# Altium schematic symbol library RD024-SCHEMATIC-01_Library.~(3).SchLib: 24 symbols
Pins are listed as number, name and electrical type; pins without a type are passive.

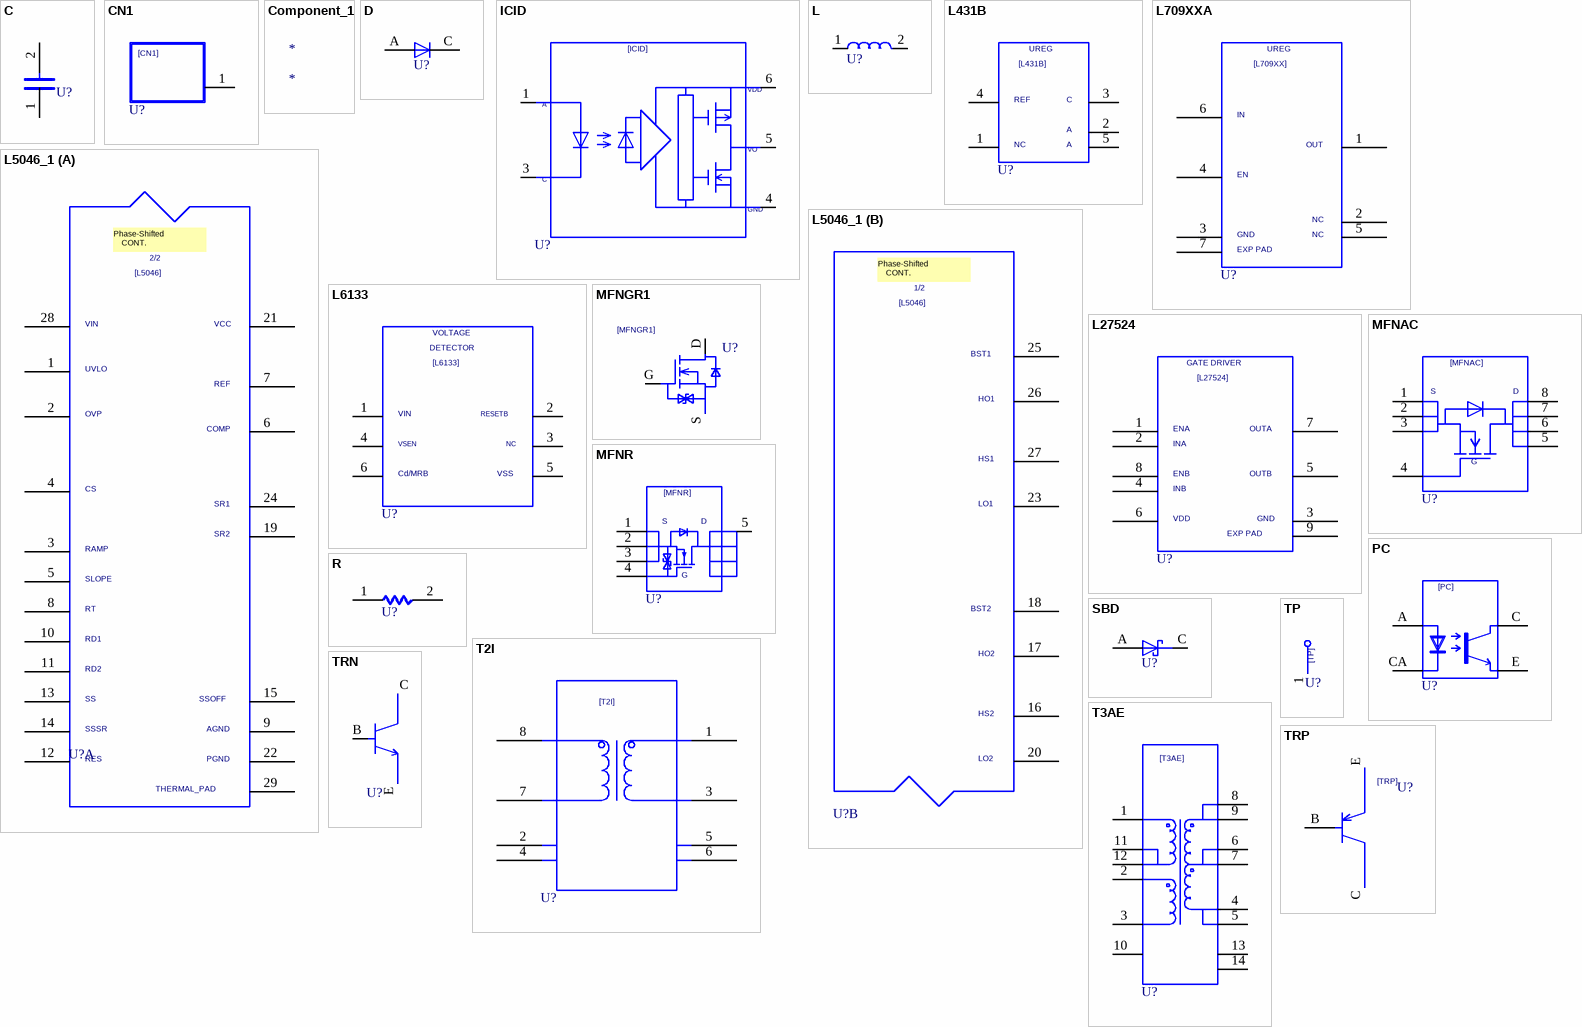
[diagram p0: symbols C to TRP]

## C
designator U?  (value not drawn)
OriginalSymbolOrigin: (2540,7620); Altium-Right: 20; Altium-Bottom: 10
pins: 1, 2

## CN1
designator U?  (value not drawn)
OriginalSymbolOrigin: (2540,12700); Altium-Right: 50; Altium-Bottom: 40
pins: 1

## Component_1
designator *

## D
designator U?  (value not drawn)
SAVEAREA0: -225,-91,12804,7836; SAVECOUNT: 3; TIME: 14:49:55; UPDATEUSER: 19870035; UPDATETIME: 14:20:16; OriginalSymbolOrigin: (5080,5080); Altium-Right: 10; Altium-Bottom: 20
pins: A, C

## ICID
designator U?  (value not drawn)
TIME: 11:37:10; UPDATEUSER: cae; UPDATETIME: 10:02:13; SAVECOUNT: 16; SAVEAREA0: -15781,-397,59072,38480; OriginalSymbolOrigin: (2540,35560); Altium-Right: 150; Altium-Bottom: 130
pins: 1, 3, 4, 5, 6

## L
designator U?  (value not drawn)
OriginalSymbolOrigin: (2540,5080); Altium-Right: 30; Altium-Bottom: 20
pins: 1, 2

## L431B
designator U?  (value not drawn)
SAVEAREA0: -12224,-318,37706,25614; TIME: 11:47:14; UPDATEUSER: cae; UPDATETIME: 15:43:57; SAVECOUNT: 6; OriginalSymbolOrigin: (5080,22860); Altium-Right: 60; Altium-Bottom: 80
pins: 1, 2, 3, 4, 5

## L709XXA
designator U?  (value not drawn)
SAVECOUNT: 38; SAVEAREA0: -24553,-450,60279,43610; TIME: 14:46:30; UPDATEUSER: cae; UPDATETIME: 12:49:59; OriginalSymbolOrigin: (7620,40640); Altium-Right: 80; Altium-Bottom: 150
pins: 1, 2, 3, 4, 5, 6, 7

## L5046_1
designator U?  (value not drawn)
SAVEAREA0: -71804,-1007,117827,97484; TIME: 14:38:41; UPDATEUSER: cae; UPDATETIME: 09:49:47; SAVECOUNT: 16; OriginalSymbolOrigin: (7620,93980); Altium-Right: 120; Altium-Bottom: 410; Altium-Bottom1: 370
part A pins: 1, 2, 3, 4, 5, 6, 7, 8, 9, 10, 11, 12, 13, 14, 15, 19, 21, 22, 24, 28, 29
part B pins: 16, 17, 18, 20, 23, 25, 26, 27

## L6133
designator U?  (value not drawn)
TIME: 13:21:52; UPDATEUSER: cae; UPDATETIME: 10:15:35; SAVECOUNT: 15; SAVEAREA0: -9663,-435,45411,35893; OriginalSymbolOrigin: (5080,33020); Altium-Right: 100; Altium-Bottom: 120
pins: 1, 2, 3, 4, 5, 6

## L27524
designator U?  (value not drawn)
SAVEAREA0: -18325,-397,56528,38480; SAVECOUNT: 17; TIME: 12:23:18; UPDATEUSER: cae; UPDATETIME: 15:16:57; OriginalSymbolOrigin: (7620,35560); Altium-Right: 90; Altium-Bottom: 130
pins: 1, 2, 3, 4, 5, 6, 7, 8, 9

## MFNAC
designator U?  (value not drawn)
TIME: 18:29:30; UPDATEUSER: 19990028; UPDATETIME: 14:45:16; SAVECOUNT: 26; SAVEAREA0: -10143,-336,37609,28718; OriginalSymbolOrigin: (5080,25400); Altium-Right: 70; Altium-Bottom: 90
pins: 1, 2, 3, 4, 5, 6, 7, 8

## MFNGR1
designator U?  (value not drawn)
SAVECOUNT: 24; SAVEAREA0: -14204,-8572,26849,21288; TIME: 16:49:03; UPDATEUSER: ikeda-k; UPDATETIME: 18:49:38; OriginalSymbolOrigin: (2540,10160); Altium-Right: 40
pins: D, G, S

## MFNR
designator U?  (value not drawn)
SAVEAREA0: -11373,-4619,33654,28142; TIME: 18:57:44; UPDATEUSER: ikeda-k; UPDATETIME: 16:18:19; SAVECOUNT: 11; OriginalSymbolOrigin: (5080,20320); Altium-Right: 60; Altium-Bottom: 70
pins: 1, 2, 3, 4, 5

## PC
designator U?  (value not drawn)
OriginalSymbolOrigin: (5080,17780); Altium-Right: 50; Altium-Bottom: 70
pins: A, C, CA, E

## R
designator U?  (value not drawn)
OriginalSymbolOrigin: (5080,5080); Altium-Right: 20
pins: 1, 2

## SBD
designator U?  (value not drawn)
SAVEAREA0: -4630,-153,17114,13055; TIME: 14:49:55; UPDATEUSER: fukuda-y; UPDATETIME: 08:16:22; SAVECOUNT: 9; OriginalSymbolOrigin: (5080,5080); Altium-Right: 20
pins: A, C

## T2I
designator U?  (value not drawn)
SAVEAREA0: -21366,-459,62077,41078; SAVECOUNT: 8; TIME: 14:27:07; UPDATEUSER: 19990028; UPDATETIME: 13:00:08; OriginalSymbolOrigin: (7620,38100); Altium-Right: 100; Altium-Bottom: 140
pins: 1, 2, 3, 4, 5, 6, 7, 8

## T3AE
designator U?  (value not drawn)
SAVEAREA0: -34674,-485,56770,47009; TIME: 17:49:49; UPDATEUSER: cae; UPDATETIME: 15:15:30; SAVECOUNT: 3; OriginalSymbolOrigin: (5080,43180); Altium-Right: 50; Altium-Bottom: 160
pins: 1, 2, 3, 4, 5, 6, 7, 8, 9, 10, 11, 12, 13, 14

## TP
designator U?  (value not drawn)
TIME: 16:12:21; UPDATEUSER: fukuda-y; UPDATETIME: 16:18:11; SAVECOUNT: 2; SAVEAREA0: -242,-92,12810,7836; OriginalSymbolOrigin: (0,7620); Altium-Right: 20; Altium-Bottom: 30
pins: 1

## TRN
designator U?  (value not drawn)
TIME: 09:39:04; UPDATEUSER: 19910145; UPDATETIME: 15:12:10; SAVECOUNT: 8; SAVEAREA0: -6194,-158,18648,15662; OriginalSymbolOrigin: (2540,17780); Altium-Right: 20; Altium-Bottom: 80
pins: B, C, E

## TRP
designator U?  (value not drawn)
TIME: 09:39:04; UPDATEUSER: 19870035; UPDATETIME: 15:34:42; SAVECOUNT: 12; SAVEAREA0: -5466,-244,29263,20886; OriginalSymbolOrigin: (5080,22860); Altium-Right: 20; Altium-Bottom: 100
pins: B, C, E

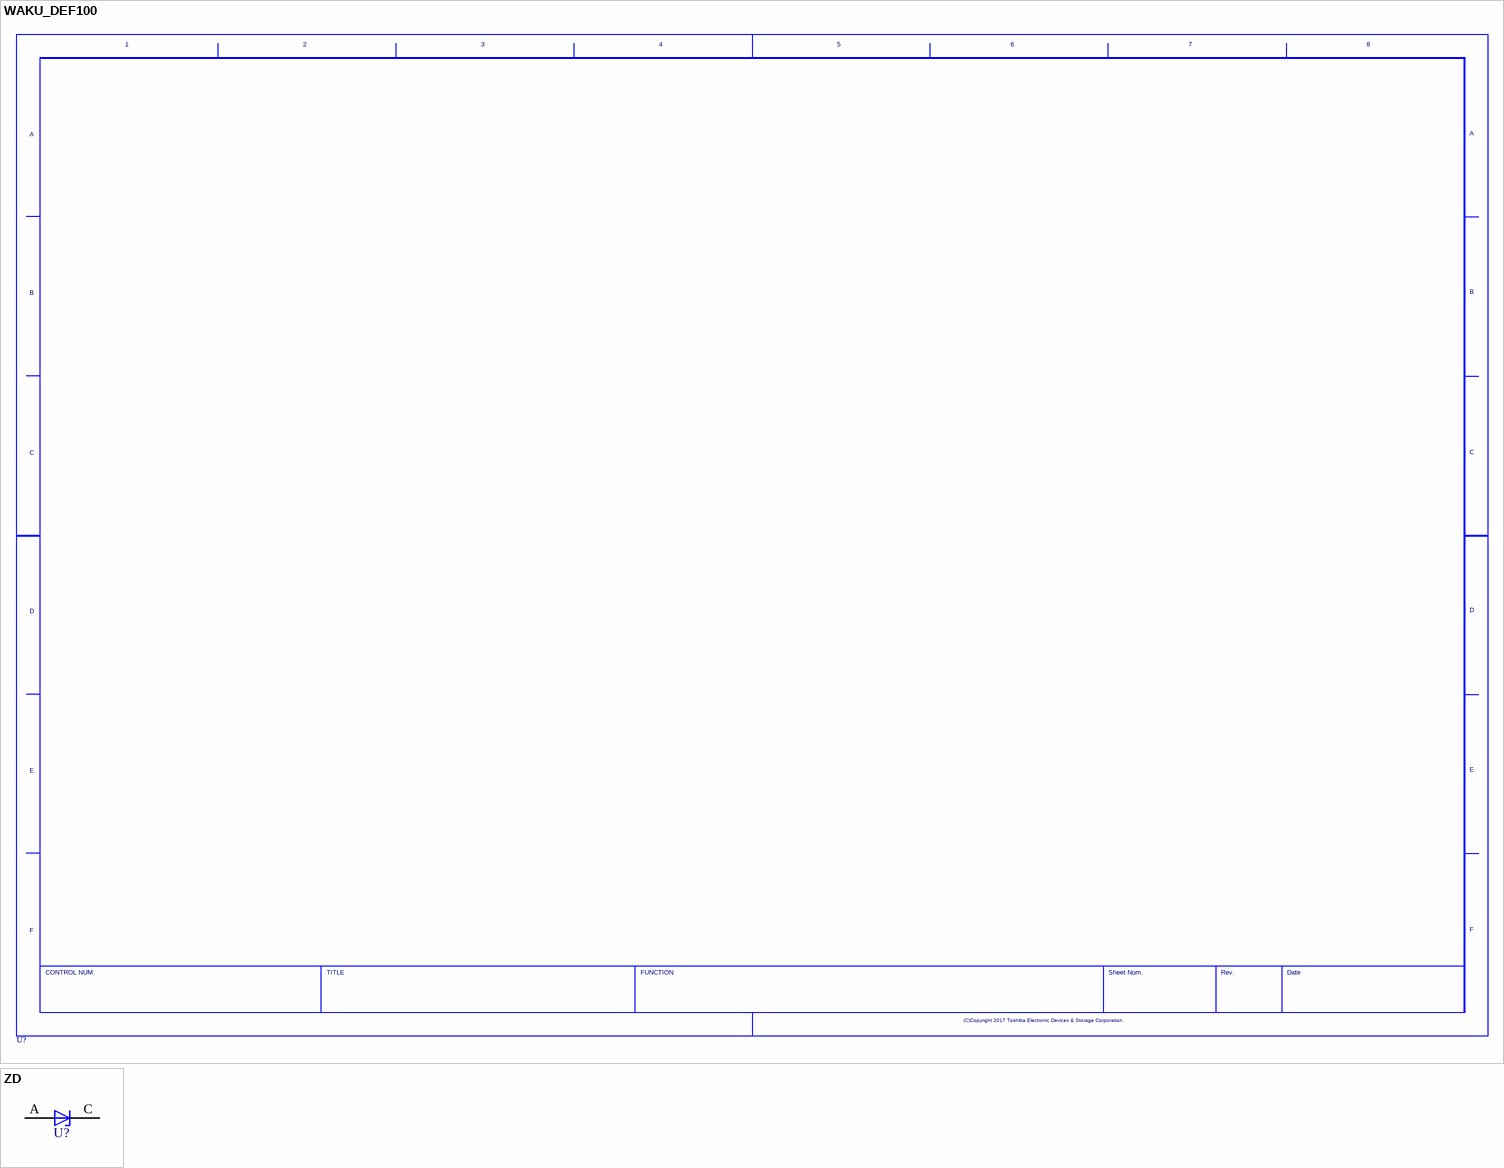
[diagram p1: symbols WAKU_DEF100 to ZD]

## WAKU_DEF100
designator U?  (value not drawn)
PLOTTIME: HH:MM; SAVEAREA0: -63393,-16950,474261,314592; TIME: 14:30:25; UPDATEUSER: cae; UPDATETIME: 18:29:18; SAVECOUNT: 3; OriginalSymbolOrigin: (10160,284480); Altium-Right: 1570; Altium-Bottom: 1070

## ZD
designator U?  (value not drawn)
SAVEAREA0: -4630,-153,17114,13055; TIME: 14:49:55; UPDATEUSER: fukuda-y; UPDATETIME: 08:18:42; SAVECOUNT: 6; OriginalSymbolOrigin: (5080,5080); Altium-Right: 10; Altium-Bottom: 20
pins: A, C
